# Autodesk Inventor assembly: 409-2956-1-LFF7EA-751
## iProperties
Created: 2010-06
Part Number: 409-2956-1-LFF7EA-751
Document SubType Name: Weldment
Designer: S. Boerckel
Mass: 5468.17 g
Surface Area: 1712.51 cm^2
Volume: 695.851 cm^3
Density: 7.85824 g/cm^3
Description: RECERCULATION SPOOL
Weld Material: Welded Steel Mild
Material: WEDLMENT
Author: S. Boerckel
Revision Number: B
Subject: DEMIN WATER FORWARDING PUMP SKID-7EA
